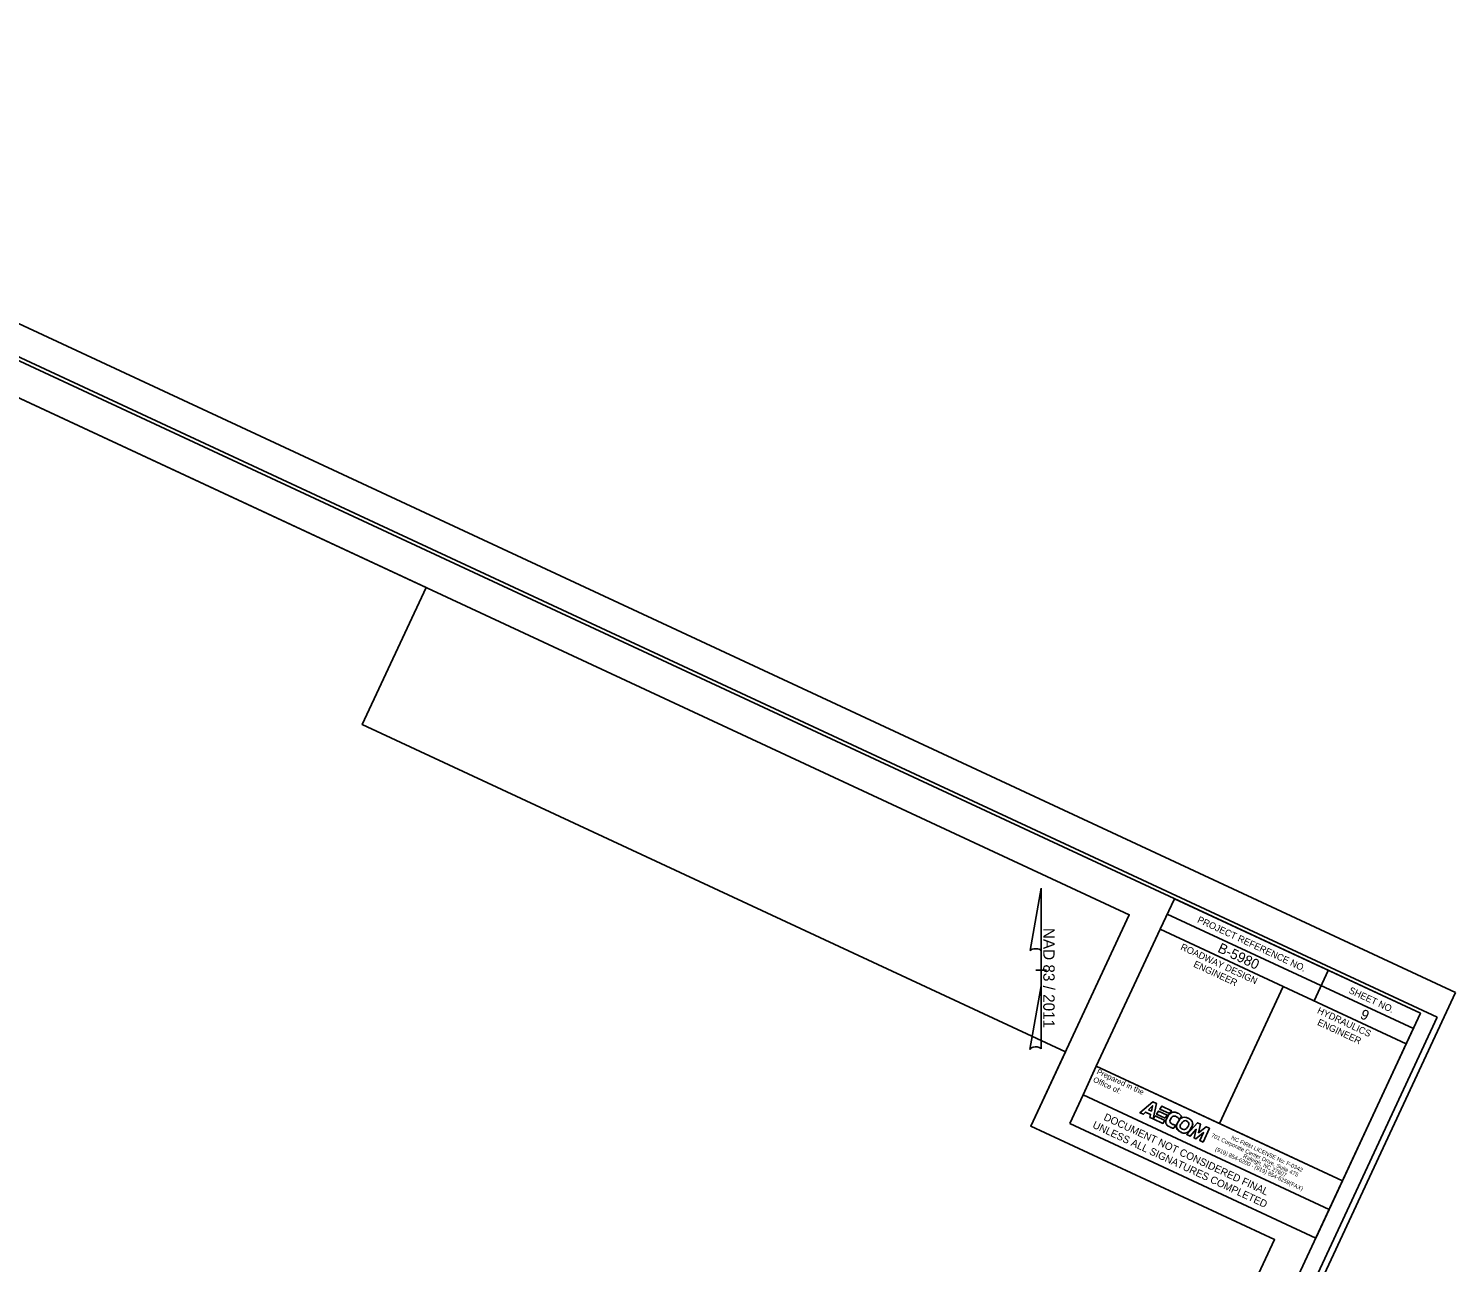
# Model space of a CAD drawing. Extents: x 2348072 to 2350078, y 842684 to 844499.
# Drawn here: x 2349016 to 2350078, y 843581 to 844499 of the extents above; entities that cross this region are included whole.
import ezdxf

# ---------------------------------------------------------------- set-up
doc = ezdxf.new("R2010")
doc.units = 0
for name, color, linetype in [('Default', 7, 'Continuous'), ('Old_Level_49', 7, 'Continuous'), ('Prop North Arrow NAD83 for Plan Sheets CELL', 7, 'Continuous'), ('Sheet Border Standard 30in CELL', 7, 'Continuous'), ('Sheet Clip Boundary CELL', 7, 'Continuous'), ('Sheet Data Field CELL', 7, 'Continuous'), ('Sheet Plot Border Inside CELL', 7, 'Continuous'), ('Sheet Plot Border Outside CELL', 7, 'Continuous'), ('Sheet Profile CELL', 7, 'Continuous'), ('Sheet Sticker Exception Certification CELL', 7, 'Continuous')]:
    doc.layers.add(name, color=color, linetype=linetype)

# ---------------------------------------------------------------- blocks, each defined once
blk = doc.blocks.new('block 2')
at = {"layer": 'Default'}
for p, q in [((0.10137, 0.08733), (0.10174, 0.08975)), ((0.10174, 0.08975), (0.10818, 0.08975)), ((0.10234, 0.09375), (0.10197, 0.09133)), ((0.10197, 0.09133), (0.10929, 0.09133)), ((0.10966, 0.09375), (0.10234, 0.09375)), ((0.10818, 0.08975), (0.10782, 0.08733)), ((0.10929, 0.09133), (0.10966, 0.09375)), ((0.10114, 0.08576), (0.10078, 0.08333)), ((0.10078, 0.08333), (0.1081, 0.08333)), ((0.10846, 0.08576), (0.10114, 0.08576)), ((0.10782, 0.08733), (0.10137, 0.08733)), ((0.1081, 0.08333), (0.10846, 0.08576))]:
    blk.add_line(p, q, dxfattribs=at)
for points in [[(0.10782, 0.08733), (0.10137, 0.08733), (0.10174, 0.08975), (0.10818, 0.08975), (0.10782, 0.08733)], [(0.10929, 0.09133), (0.10197, 0.09133), (0.10234, 0.09375), (0.10966, 0.09375), (0.10929, 0.09133)], [(0.10846, 0.08576), (0.10114, 0.08576), (0.10078, 0.08333), (0.1081, 0.08333), (0.10846, 0.08576)]]:
    blk.add_lwpolyline(points, dxfattribs=at)
blk = doc.blocks.new('block 3')
at = {"layer": 'Default'}
blk.add_open_spline([(0.12275, 0.09393), (0.12554, 0.09373), (0.12726, 0.09146), (0.12695, 0.08843), (0.12663, 0.08531), (0.12411, 0.08298), (0.12127, 0.08318), (0.11848, 0.08338), (0.11676, 0.08565), (0.11707, 0.08868), (0.11739, 0.0918), (0.11991, 0.09413), (0.12275, 0.09393)], degree=3, dxfattribs=at)

msp = doc.modelspace()

# ---------------------------------------------------------------- linework, layer by layer
at = {"layer": 'Default'}
for p, q in [((2349800.5, 843705.5), (2349983.6, 843620.3)), ((2349790.6, 843684.2), (2349973.7, 843599))]:
    msp.add_line(p, q, dxfattribs=at)
at = {"layer": 'Old_Level_49'}
for p, q in [((2349852.4, 843700.3), (2349842.8, 843692.3)), ((2349849.1, 843694.5), (2349852.3, 843697.4)), ((2349852.3, 843697.4), (2349851.4, 843693.5)), ((2349852.3, 843697.4), (2349852.3, 843697.4)), ((2349855.2, 843699), (2349852.4, 843700.3)), ((2349852.8, 843687.6), (2349855.2, 843699)), ((2349842.8, 843692.3), (2349845.4, 843691.1)), ((2349845.4, 843691.1), (2349847.1, 843692.7)), ((2349847.1, 843692.7), (2349850.8, 843691)), ((2349851.4, 843693.5), (2349849.1, 843694.5)), ((2349850.8, 843691), (2349850.3, 843688.8)), ((2349850.3, 843688.8), (2349852.8, 843687.6)), ((2349885.7, 843684.8), (2349877.7, 843676)), ((2349888, 843683.7), (2349885.7, 843684.8)), ((2349877.7, 843676), (2349880.3, 843674.8)), ((2349880.3, 843674.8), (2349884.8, 843680)), ((2349884.8, 843680), (2349883.1, 843673.5)), ((2349884.4, 843672.9), (2349890.2, 843677.5)), ((2349886.5, 843677.4), (2349888, 843683.7)), ((2349892.2, 843681.8), (2349886.5, 843677.4)), ((2349890.2, 843677.5), (2349887.4, 843671.5)), ((2349889.9, 843670.4), (2349894.5, 843680.7)), ((2349894.5, 843680.7), (2349892.2, 843681.8)), ((2349883.1, 843673.5), (2349884.4, 843672.9)), ((2349887.4, 843671.5), (2349889.9, 843670.4))]:
    msp.add_line(p, q, dxfattribs=at)
for points in [[(2349850.3, 843688.8), (2349852.8, 843687.6), (2349855.2, 843699), (2349852.4, 843700.3), (2349842.8, 843692.3), (2349845.4, 843691.1), (2349847.1, 843692.7), (2349850.8, 843691), (2349850.3, 843688.8)], [(2349849.1, 843694.5), (2349852.3, 843697.4), (2349852.3, 843697.4), (2349851.4, 843693.5), (2349849.1, 843694.5)], [(2349889.9, 843670.4), (2349894.5, 843680.7), (2349892.2, 843681.8), (2349886.5, 843677.4), (2349888, 843683.7), (2349885.7, 843684.8), (2349877.7, 843676), (2349880.3, 843674.8), (2349884.8, 843680), (2349883.1, 843673.5), (2349884.4, 843672.9), (2349890.2, 843677.5), (2349887.4, 843671.5), (2349889.9, 843670.4)]]:
    msp.add_lwpolyline(points, dxfattribs=at)
for points in [[(2349869.5, 843683.1), (2349868.6, 843683.1), (2349867.6, 843683.5), (2349867.1, 843683.7), (2349865.5, 843684.5), (2349864.9, 843686.1), (2349865.7, 843687.7), (2349866.6, 843689.4), (2349868.5, 843690), (2349870.3, 843689.2), (2349871.1, 843688.8), (2349871.7, 843688.2), (2349872.1, 843687.3), (2349872.1, 843687.3), (2349873.8, 843689.6), (2349873.8, 843689.6), (2349873, 843690.6), (2349872.3, 843691.3), (2349871.2, 843691.8), (2349868.3, 843693.1), (2349864.7, 843691.8), (2349863.1, 843688.8), (2349861.7, 843685.8), (2349862.6, 843682.8), (2349865.5, 843681.5), (2349866, 843681.2), (2349867.1, 843680.8), (2349868, 843680.8), (2349868, 843680.8), (2349869.5, 843683.1), (2349869.5, 843683.1)], [(2349869.5, 843683.1), (2349868.6, 843683.1), (2349867.6, 843683.5), (2349867.1, 843683.7), (2349865.5, 843684.5), (2349864.9, 843686.1), (2349865.7, 843687.7), (2349866.6, 843689.4), (2349868.5, 843690), (2349870.3, 843689.2), (2349871.1, 843688.8), (2349871.7, 843688.2), (2349872.1, 843687.3), (2349872.1, 843687.3), (2349873.8, 843689.6), (2349873.8, 843689.6), (2349873, 843690.6), (2349872.3, 843691.3), (2349871.2, 843691.8), (2349868.3, 843693.1), (2349864.7, 843691.8), (2349863.1, 843688.8), (2349861.7, 843685.8), (2349862.6, 843682.8), (2349865.5, 843681.5), (2349866, 843681.2), (2349867.1, 843680.8), (2349868, 843680.8), (2349868, 843680.8), (2349869.5, 843683.1), (2349869.5, 843683.1)], [(2349871.9, 843678.8), (2349870.1, 843680.4), (2349869.8, 843683), (2349871.2, 843685.4), (2349873, 843688.4), (2349876.5, 843689.5), (2349879.2, 843688)], [(2349879.2, 843688), (2349881.9, 843686.5), (2349882.5, 843683.5), (2349880.8, 843680.7), (2349879.1, 843677.8), (2349875.5, 843676.6), (2349872.8, 843678.1), (2349872.5, 843678.3), (2349872.2, 843678.6), (2349871.9, 843678.8)], [(2349878.3, 843681.6), (2349879.5, 843683.1), (2349879.4, 843684.8), (2349878.3, 843685.6), (2349877, 843686.6), (2349875.1, 843686.1), (2349873.9, 843684.5), (2349872.7, 843682.9), (2349872.7, 843681.3), (2349873.9, 843680.4), (2349875.2, 843679.4), (2349877, 843679.9), (2349878.3, 843681.6)], [(2349878.3, 843681.6), (2349879.5, 843683.1), (2349879.4, 843684.8), (2349878.3, 843685.6), (2349877, 843686.6), (2349875.1, 843686.1), (2349873.9, 843684.5), (2349872.7, 843682.9), (2349872.7, 843681.3), (2349873.9, 843680.4), (2349875.2, 843679.4), (2349877, 843679.9), (2349878.3, 843681.6)]]:
    msp.add_open_spline(points, degree=3, dxfattribs=at)
at = {"layer": 'Prop North Arrow NAD83 for Plan Sheets CELL'}
for p, q in [((2349761.1, 843812.9), (2349769.3, 843859.3)), ((2349769.4, 843859.3), (2349769.4, 843811.5)), ((2349769.4, 843786.7), (2349769.4, 843812.9)), ((2349769.4, 843811.5), (2349769.4, 843812.9)), ((2349765.4, 843798.3), (2349765.3, 843798.3)), ((2349765.4, 843798.3), (2349773.4, 843798.3)), ((2349768.9, 843798.3), (2349765.4, 843798.3)), ((2349769.4, 843786.7), (2349761, 843739.4)), ((2349769.4, 843739.7), (2349769.4, 843786.7))]:
    msp.add_line(p, q, dxfattribs=at)
for centre, start_param, end_param in [((2349765.3, 843812.4), 0.211319, 2.90315), ((2349765.3, 843739.3), 0.19626, 3.136524)]:
    msp.add_ellipse(centre, major_axis=(4.23, 0.02), ratio=0.461128, start_param=start_param, end_param=end_param, dxfattribs=at)
at = {"layer": 'Sheet Border Standard 30in CELL'}
for p, q in [((2349863.2, 843840.1), (2350046.3, 843754.9)), ((2349857.9, 843828.8), (2350041, 843743.6)), ((2349857.9, 843828.8), (2350041, 843743.6)), ((2349982.9, 843798.2), (2349972.4, 843775.5)), ((2349949.5, 843786.2), (2349902, 843684.2))]:
    msp.add_line(p, q, dxfattribs=at)
for points in [[(2350051.6, 843766.3), (2348678.7, 844405.4), (2348235.6, 843453.5), (2349608.4, 842814.4)], [(2349868.5, 843851.5), (2350051.6, 843766.3), (2350041, 843743.6), (2349857.9, 843828.8)], [(2349857.9, 843828.8), (2349949.5, 843786.2), (2349902, 843684.2), (2349810.4, 843726.8)], [(2349949.5, 843786.2), (2350041, 843743.6), (2349993.5, 843641.6), (2349902, 843684.2)]]:
    msp.add_lwpolyline(points, close=True, dxfattribs=at)
at = {"layer": 'Sheet Clip Boundary CELL'}
for points in [[(2348757.8, 844341), (2348345.6, 843455.4), (2349604, 842869.6), (2349943, 843597.8), (2349761.6, 843682.2), (2349834.9, 843839.6)], [(2349311.6, 844083.2), (2348757.8, 844341), (2348401, 843574.5), (2348593.8, 843484.7), (2348538.4, 843365.7), (2349604, 842869.6), (2349943, 843597.8), (2349761.6, 843682.2), (2349787.4, 843737.5), (2349264.1, 843981.1)]]:
    msp.add_lwpolyline(points, close=True, dxfattribs=at)
at = {"layer": 'Sheet Plot Border Inside CELL'}
msp.add_lwpolyline([(2350064.1, 843763.3), (2348538.8, 844473.3), (2348093.5, 843516.8), (2349618.8, 842806.7)], close=True, dxfattribs=at)
at = {"layer": 'Sheet Plot Border Outside CELL'}
msp.add_lwpolyline([(2350077.6, 843781.7), (2348536.5, 844499.2), (2348072.2, 843501.9), (2349613.4, 842784.5)], close=True, dxfattribs=at)
at = {"layer": 'Sheet Profile CELL'}
msp.add_line((2349810.4, 843726.8), (2349800.5, 843705.5), dxfattribs=at)
at = {"layer": 'Sheet Sticker Exception Certification CELL'}
for p, q in [((2349800.5, 843705.5), (2349810.4, 843726.8)), ((2349810.4, 843726.8), (2349993.5, 843641.6)), ((2349790.6, 843684.2), (2349800.5, 843705.5)), ((2349983.6, 843620.3), (2349800.5, 843705.5)), ((2349800.5, 843705.5), (2349983.6, 843620.3)), ((2349973.7, 843599), (2349790.6, 843684.2)), ((2349993.5, 843641.6), (2349983.6, 843620.3)), ((2349983.6, 843620.3), (2349973.7, 843599))]:
    msp.add_line(p, q, dxfattribs=at)

# ---------------------------------------------------------------- block references
at = {"layer": 'Old_Level_49', "xscale": 1084.8432715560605, "yscale": 1084.8432715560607, "rotation": -24.966727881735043}
for name in ['block 2', 'block 3']:
    msp.add_blockref(name, (2349715.5, 843651.8), dxfattribs=at)

# ---------------------------------------------------------------- texts
at = {"layer": 'Old_Level_49'}
for s, height, p in [('Office of:', 4.02, (2349807.6, 843715.5)), ('Prepared in the ', 4.018, (2349810.3, 843721.4)), ('701 Corporate Center Drive, Suite 475', 3.013, (2349895.6, 843674.4)), ('NC FIRM LICENSE No: F-0342', 3.013, (2349910.4, 843672.6)), ('(919) 854-6200 - (919) 854-6259(FAX)', 3.013, (2349898.6, 843664.2)), ('Raleigh, NC 27607', 3.013, (2349919.3, 843659))]:
    msp.add_text(s, height=height, rotation=335.0333, dxfattribs=at).set_placement(p)
at = {"layer": 'Prop North Arrow NAD83 for Plan Sheets CELL'}
msp.add_text('NAD 83 / 2011', height=8.501, rotation=270, dxfattribs=at).set_placement((2349770.9, 843829.8))
at = {"layer": 'Sheet Border Standard 30in CELL'}
for s, p in [('PROJECT REFERENCE NO.', (2349885.1, 843834.2)), ('ROADWAY DESIGN', (2349872.6, 843813.9)), ('ENGINEER', (2349882.2, 843801.1)), ('SHEET NO.', (2349997.8, 843781.6)), ('HYDRAULICS', (2349974.3, 843766.6)), ('ENGINEER', (2349974.4, 843757.8))]:
    msp.add_text(s, height=5, rotation=335.0369, dxfattribs=at).set_placement(p)
at = {"layer": 'Sheet Data Field CELL'}
for s, p in [('B-5980', (2349900.1, 843812.2)), ('9', (2350006.1, 843762.9))]:
    msp.add_text(s, height=7.5, rotation=335.0369, dxfattribs=at).set_placement(p)
at = {"layer": 'Sheet Sticker Exception Certification CELL'}
for s, p in [('UNLESS ALL SIGNATURES COMPLETED', (2349807.1, 843681.3)), ('DOCUMENT NOT CONSIDERED FINAL', (2349815.4, 843687.1))]:
    msp.add_text(s, height=5.5, rotation=335.0369, dxfattribs=at).set_placement(p)

doc.saveas('drawing.dxf')
